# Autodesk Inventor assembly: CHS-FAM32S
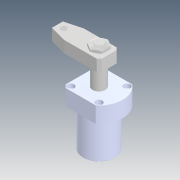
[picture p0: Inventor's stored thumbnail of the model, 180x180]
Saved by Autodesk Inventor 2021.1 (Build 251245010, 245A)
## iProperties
Created: 2020-02
Part Number: CHS-FAM32S
Description: STEP AP214
Document SubType Name: Assembly
Designer: user
Title: chs-fam32s_asm.STEP
Revision Number: ÈÎºÎ
Sending System: SolidWorks 2016
Preprocessor: SwSTEP 2.0
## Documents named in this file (5)
- D:\Vault_2016\Projekty\Clamptek\Hydraulic\CHS\CHS-32\Inventor\CHS-FAM32S\CHS-FAM32S.iam
- D:\Vault_2016\Projekty\Clamptek\Hydraulic\CHS\CHS-32\Inventor\CHS-FAM32S\CHS-32S-02_2_1.ipt
- D:\Vault_2016\Projekty\Clamptek\Hydraulic\CHS\CHS-32\Inventor\CHS-FAM32S\CHS-32S-01_3.ipt
- D:\Vault_2016\Projekty\Clamptek\Hydraulic\CHS\CHS-32\Inventor\CHS-FAM32S\M16_3.ipt
- D:\Vault_2016\Projekty\Clamptek\Hydraulic\CHS\CHS-32\Inventor\CHS-FAM32S\CHS-FAM32BT.ipt
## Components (4 placed, 4 different names)
1. CHS-32S-02_2_1_1
2. CHS-32S-01_3_2
3. M16_3_3
4. CHS-FAM32BT_4
